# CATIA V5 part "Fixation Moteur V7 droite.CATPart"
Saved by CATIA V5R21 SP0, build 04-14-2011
Part number: MOTEURDROIT
Bounding box of the stored display mesh (mm): x -4.2 to 4.2, y -40 to 0, z -20 to 40
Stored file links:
  C:\Users\2027.DESARCY-LEMIE30\Desktop\Assemblage26.05\Fixation Moteur V7 droite.CATPart
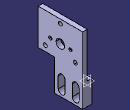
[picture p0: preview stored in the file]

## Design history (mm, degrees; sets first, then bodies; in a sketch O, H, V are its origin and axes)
Body1 (main body)
  Sketch1 on yz-plane, origin (0, 0, 0), H (0, 1, 0), V (0, 0, 1)
    line L1 (-40, 40) -> (0, 40)
    line L2 (0, 40) -> (0, 0)
    line L3 (0, 0) -> (-40, 0)
    line L4 (-40, 0) -> (-40, 40)
    point P3 (0, 0)
    length L4 = 40
    length L1 = 40
    horizontal: L1 H, L3 H
    vertical: L2 V, L4 V
    coincidence: P3 O
  Pad1: profile Sketch1, direction (1, 0, 0), length 4.2
  Sketch2 on end face of Pad1, origin (4.2, 0, 0), H (0, 1, 0), V (0, 0, 1)
    line L1 (-25, 0) -> (0, 0)
    line L2 (0, 0) -> (0, -20)
    line L3 (0, -20) -> (-25, -20)
    line L4 (-25, -20) -> (-25, 0)
    point P2 (0, 0)
    length L2 = 20
    length L3 = 25
    horizontal: L1 H, L3 H
    vertical: L2 V, L4 V
    coincidence: P2 O
  Pad2: profile Sketch2, direction (-1, 0, 0), length 8.4
  Sketch3 on end face of Pad2, origin (-4.2, 0, 0), H (0, -1, 0), V (0, 0, 1)
    point P1 (3.15, -5)
    line L1 (9.35, -5) -> (9.35, -15)
    line L2 (3.15, -15) -> (3.15, -5)
    point P2 (9.35, -5)
    point P3 (9.35, -15)
    point P4 (3.15, -15)
    axis line L3 (12.5, 2.3624) -> (12.5, -21.6714)
    reference projected line E1 (25, 0) -> (25, -20) from edge [end face of Pad2 | face of Pad2 from Sketch2.L4]
    arc A1 centre (6.25, -5) radius 3.1 from (9.35, -5) to (3.15, -5) ccw
    point P8 (10.7649, -15.4491)
    arc A2 centre (6.25, -15) radius 3.1 from (3.15, -15) to (9.35, -15) ccw
    point P9 (6.25, -15)
    point P10 (3.15, -15)
    point P11 (9.35, -15)
    point P12 (21.85, -5)
    point P13 (21.85, -15)
    line L4 (21.85, -15) -> (21.85, -5)
    point P14 (15.65, -5)
    arc A3 centre (18.75, -5) radius 3.1 from (15.65, -5) to (21.85, -5) cw
    point P16 (15.65, -15)
    line L5 (15.65, -5) -> (15.65, -15)
    point P17 (15.65, -15)
    point P18 (21.85, -15)
    point P19 (18.75, -15)
    arc A4 centre (18.75, -15) radius 3.1 from (21.85, -15) to (15.65, -15) cw
    reference projected line E2 (25, -20) -> (0, -20) from edge [end face of Pad2 | face of Pad2 from Sketch2.L3]
    distance L3 E1 = 12.5
    radius A1 = 3.1
    distance P9 P19 = 12.5
    length L4 = 10
    distance A4 E2 = 1.9
    vertical: L1 V, L2 V, L3 V
    tangency: A1 L1, A1 L2, A2 L1, A2 L2
    coincidence: P4 A2, L1 P11, L2 P10, P3 P11, P4 P10, P13 P18, P16 P17
    symmetry: P1 P12 L3, P4 P13 L3, L2 L4 L3, P2 P14 L3, A1 A3 L3, P3 P16 L3, L1 L5 L3, P11 P17 L3, P10 P18 L3, A2 A4 L3
  Pocket1: profile Sketch3, direction (1, 0, 0), through (limit type 3)
  Sketch4 on start face of Pad1, origin (0, 0, 0), H (0, -1, 0), V (0, 0, 1)
    construction line L1 (0, 20.75) -> (40, 20.75)
    point P1 (0, 20.75)
    point P2 (40, 20.75)
    reference projected line E1 (0, 40) -> (40, 40) from edge [start face of Pad1 | face of Pad1 from Sketch1.L1]
    reference projected line E2 (0, 0) -> (0, 40) from edge [start face of Pad1 | face of Pad2]
    reference projected line E3 (40, 40) -> (40, 0) from edge [start face of Pad1 | face of Pad1 from Sketch1.L4]
    construction line L2 (20, 40) -> (20, 0)
    point P3 (20, 40)
    point P4 (20, 0)
    reference projected line E4 (0, 40) -> (40, 40) from edge [start face of Pad1 | face of Pad1 from Sketch1.L1]
    reference projected line E5 (40, 0) -> (0, 0) from edge [start face of Pad1 | face of Pad1 from Sketch1.L3]
    reference projected line E6 (40, 40) -> (40, 0) from edge [start face of Pad1 | face of Pad1 from Sketch1.L4]
    circle A1 centre (20, 20.75) radius 4
    point P5 (20, 20.75)
    construction line L3 (20, 20.75) -> (0, 9.203)
    point P6 (0, 9.203)
    axis line L4 (20, 20.75) -> (40, 9.203)
    point P7 (40, 9.203)
    reference projected line E7 (40, 40) -> (40, 0) from edge [start face of Pad1 | face of Pad1 from Sketch1.L4]
    circle A2 centre (20, 36.3385) radius 1.75
    point P8 (20, 36.3385)
    point P9 (33.5, 12.9558)
    circle A3 centre (33.5, 12.9558) radius 1.75
    point P10 (6.5, 12.9558)
    circle A4 centre (6.5, 12.9558) radius 1.75
    distance E1 L1 = 19.25
    distance L2 E6 = 20
    radius A1 = 4
    angle L3 L2 = 120
    angle L2 L4 = 120
    radius A2 = 1.75
    distance P9 P10 = 27
    coincidence: P1 E2, P2 E3, E4 P3, P4 E5, P6 V, P7 E7, P8 L2, P5 L1, P5 L2
    vertical: L2 V
    symmetry: A2 A3 L3, A3 A4 L2
  Pocket2: profile Sketch4, direction (1, 0, 0), through (limit type 3)
  Sketch5 on start face of Pad1, origin (0, 0, 0), H (0, -1, 0), V (0, 0, 1)
    point P1 (40, 0)
    line L1 (40, 0) -> (25, 0)
    line L2 (25, 0) -> (25, 8)
    line L3 (25, 8) -> (40, 8)
    line L4 (40, 8) -> (40, 0)
    reference projected line E1 (0, -20) -> (0, 0) from edge [end face of Pad2 | face of Pad2 from Sketch2.L2]
    reference projected line E2 (25, 0) -> (25, -20) from edge [end face of Pad2 | face of Pad2 from Sketch2.L4]
    reference projected point E3 (40, 0) from vertex [face of Pad1 from Sketch1.L3 | start face of Pad1 | face of Pad1 from Sketch1.L4]
    length L2 = 8
    length L3 = 15
    distance E1 E2 = 25 (reference)
    horizontal: L1 H, L3 H
    vertical: L2 V, L4 V
    coincidence: P1 E3
  Pocket3: profile Sketch5, direction (1, 0, 0), through (limit type 3)
  Sketch6 on start face of Pad1, origin (0, -33.8289, 21.1001), H (0, 1, 0), V (0, 0, -1)
    point P1 (22.8289, 0.3501)
    axis line L1 (13.8289, 0.3501) -> (40.6944, 0.3501)
    point P2 (13.8289, 0.3501)
    reference projected circle E1 centre (13.8289, 0.3501) radius 4 from edge [start face of Pad1 | face of Pocket2 from Sketch4.A1]
    reference projected circle E2 centre (13.8289, 0.3501) radius 4 from edge [start face of Pad1 | face of Pocket2 from Sketch4.A1]
    distance P1 E2 = 5
    horizontal: L1 H
    concentricity: P2 E1
    coincidence: P1 L1
  Hole1: placed by Sketch6, at (0, -11, 20.75) direction (1, 0, 0), diameter 3, through (limit type 6), counterbore diameter 6, counterbore depth 3
  RectPattern1: of Hole1, direction 1 instances 2, spacing 18, along face of Pad1 from Sketch1.L1 reversed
